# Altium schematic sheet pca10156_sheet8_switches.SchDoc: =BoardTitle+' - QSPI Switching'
size A3; Organization: Nordic Semiconductor; DocumentNumber: 8; SheetNumber: 8; SheetTotal: 8; CompanyName: Nordic Semiconductor; DocumentSize: A4
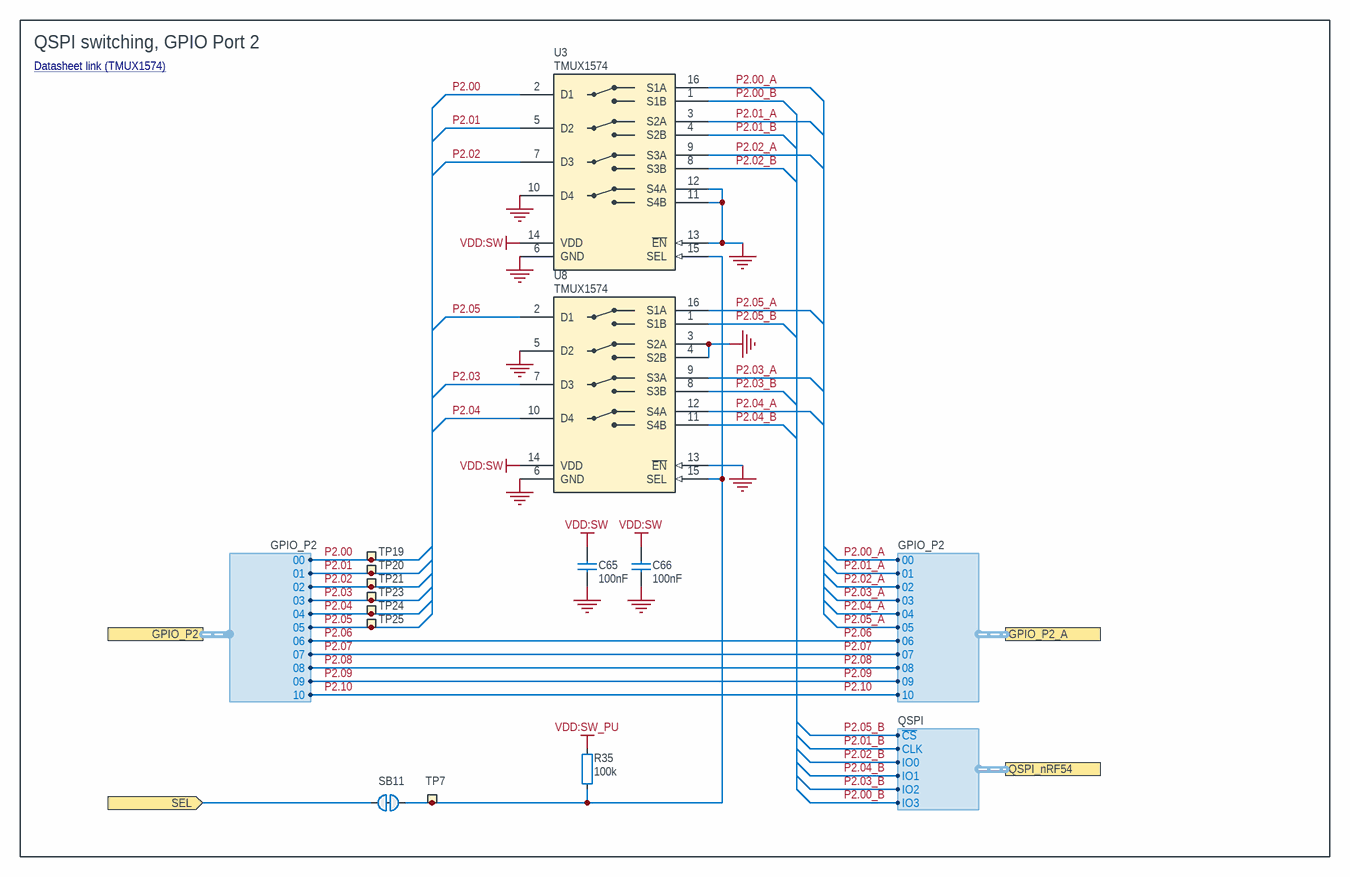
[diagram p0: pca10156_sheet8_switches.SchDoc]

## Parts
C65  100nF  [CAPC0603X03L_C]
C66  100nF  [CAPC0603X03L_C]
R35  100k  [RESC0603X03L_C]
SB11  Solderbridge  [Solderbridge_Shorted]  (value not drawn)  (net tie, no BOM)
TP7  Ø0.7mm,SMD  [TP_SMD_D0.7mm]  (value not drawn)  (no BOM)
TP19  Ø0.7mm,SMD  [TP_SMD_D0.7mm]  (value not drawn)  (no BOM)
TP20  Ø0.7mm,SMD  [TP_SMD_D0.7mm]  (value not drawn)  (no BOM)
TP21  Ø0.7mm,SMD  [TP_SMD_D0.7mm]  (value not drawn)  (no BOM)
TP23  Ø0.7mm,SMD  [TP_SMD_D0.7mm]  (value not drawn)  (no BOM)
TP24  Ø0.7mm,SMD  [TP_SMD_D0.7mm]  (value not drawn)  (no BOM)
TP25  Ø0.7mm,SMD  [TP_SMD_D0.7mm]  (value not drawn)  (no BOM)
U3  TMUX1574  [XQFN40P180X260X50-16N]
U8  TMUX1574  [XQFN40P180X260X50-16N]

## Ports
GPIO_P2 (harness GPIO_P2), GPIO_P2_A (harness GPIO_P2), QSPI_nRF54 (harness QSPI), SEL (in)

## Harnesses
GPIO_P2: 00, 01, 02, 03, 04, 05, 06, 07, 08, 09, 10
QSPI: ~{CS}, IO0, CLK, IO1, IO2, IO3

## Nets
GND: C65.2 C66.2 U3.6(GND) U3.10(D4) U3.11(S4B) U3.12(S4A) U3.13(~{EN}) U8.3(S2A) U8.4(S2B) U8.5(D2) U8.6(GND) U8.13(~{EN})
VDD:SW: C65.1 C66.1 U3.14(VDD) U8.14(VDD)
VDD:SW_PU: R35.2
P2.00: TP19.1 U3.2(D1) ; port GPIO_P2.00
P2.00_A: U3.16(S1A) ; port GPIO_P2_A.00
P2.00_B: U3.1(S1B) ; port QSPI_nRF54.IO3
P2.01: TP20.1 U3.5(D2) ; port GPIO_P2.01
P2.01_A: U3.3(S2A) ; port GPIO_P2_A.01
P2.01_B: U3.4(S2B) ; port QSPI_nRF54.CLK
P2.02: TP21.1 U3.7(D3) ; port GPIO_P2.02
P2.02_A: U3.9(S3A) ; port GPIO_P2_A.02
P2.02_B: U3.8(S3B) ; port QSPI_nRF54.IO0
P2.03: TP23.1 U8.7(D3) ; port GPIO_P2.03
P2.03_A: U8.9(S3A) ; port GPIO_P2_A.03
P2.03_B: U8.8(S3B) ; port QSPI_nRF54.IO2
P2.04: TP24.1 U8.10(D4) ; port GPIO_P2.04
P2.04_A: U8.12(S4A) ; port GPIO_P2_A.04
P2.04_B: U8.11(S4B) ; port QSPI_nRF54.IO1
P2.05: TP25.1 U8.2(D1) ; port GPIO_P2.05
P2.05_A: U8.16(S1A) ; port GPIO_P2_A.05
P2.05_B: U8.1(S1B) ; port QSPI_nRF54.~{CS}
P2.06: port GPIO_P2.06, port GPIO_P2_A.06
P2.07: port GPIO_P2.07, port GPIO_P2_A.07
P2.08: port GPIO_P2.08, port GPIO_P2_A.08
P2.09: port GPIO_P2.09, port GPIO_P2_A.09
P2.10: port GPIO_P2.10, port GPIO_P2_A.10
SEL: SB11.1 ; port SEL
NetR35_1: R35.1 SB11.2 TP7.1 U3.15(SEL) U8.15(SEL)

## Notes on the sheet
- QSPI switching, GPIO Port 2
- Datasheet link (TMUX1574) <https://www.ti.com/lit/ds/symlink/tmux1574.pdf?ts=1730869182960>

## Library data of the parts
C65 C66 = C0201-100n: Capacitor, X5R, ±10%; Manufacturer: N.A.; Part number IPS: 00000001248, 00000002505; Part number Norautron: 262071862; Part number NEMS: 100200078; Pad Count: 2; Note: 16V; Component Status: Active
R35 = R0201-100k: Resistor, ±1%, 0.05W; Manufacturer: N.A.; Part number IPS: 00000001419; Part number Norautron: 26108487; Part number NEMS: 100100080; Note: Chip Res 1%; Pad Count: 2; Component Status: Active
SB11 = Solderbridge Shorted: Shorted Solderbridge; Manufacturer: N.A.; Part number NEMS: 100500459; Pad Count: 2; Component Status: Active; System: Connector
TP7 TP19-TP21 TP23-TP25 = TP_SMD_Ø0.7MM: 0.7mm circular SMD testpad; Manufacturer: Nordic Semiconductor; Manufacturer Part Number: N.A.; Part number NEMS: 100500474; Component Status: Active; Pad Count: 1
U3 U8 = TMUX1574: Low-Capacitance, 2:1 (SPDT) 4-Channel, analog switch; Manufacturer: Texas Instruments; Manufacturer Part Number: TMUX1574RSVR; Part number NEMS: 101900850; Component Status: Active; Pad Count: 16; Note: N.A.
